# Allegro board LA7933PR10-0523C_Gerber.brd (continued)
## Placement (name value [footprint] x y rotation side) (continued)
Q55  -  [SSM3K7002FU_SC70-3]  288.59 61.86 270 bottom
Q56  -  [DMN3030LSS-13_SOP8L-8]  290.04 49.64 0 bottom
Q58  -  [SI3456DDV-T1-GE3_TSOP6]  138.23 147.7 90 top
Q59  -  [SSM3K7002FU_SC70-3]  294.17 54.45 270 bottom
Q60  -  [SSM3K7002FU_SC70-3]  151.16 154.1 90 top
Q61  -  [SSM3K7002FU_SC70-3]  207.87 54.04 0 bottom
Q63  -  [SI4164DY-T1-GE3_SO8]  47.47 132.3 0 top
Q65  -  [SSM3K7002FU_SC70-3]  129.57 32.83 90 top
Q66  -  [SSM3K7002FU_SC70-3]  9.31 133.92 90 bottom
Q67  -  [SSM3K7002FU_SC70-3]  216.18 90.74 90 bottom
Q68  -  [SSM3K7002FU_SC70-3]  190.53 150.43 270 bottom
Q69  -  [SSM3K7002FU_SC70-3]  290.17 55.88 0 bottom
Q70  -  [SSM3K7002FU_SC70-3]  43.53 131.82 0 bottom
Q71  -  [SSM3K7002FU_SC70-3]  125.07 72.27 0 top
Q72  -  [SSM3K7002FU_SC70-3]  235.93 53.98 180 bottom
Q73  -  [SSM3K7002FU_SC70-3]  101.77 135.45 270 top
Q74  -  [DMN66D0LDW-7_SOT363-6]  233.13 59.18 0 bottom
Q75  -  [PDTA114EU_SC70-3]  231.24 59.03 0 bottom
Q76  -  [SI4800BDY-T1-E3_SO8]  196.09 171.39 270 bottom
Q77  -  [SSM3K7002FU_SC70-3]  103.29 159.32 270 top
Q78  -  [DMN66D0LDW-7_SOT363-6]  225.76 64.51 0 bottom
Q79  -  [PDTA114EU_SC70-3]  226.16 59.03 0 bottom
Q80  -  [PDTA114EU_SC70-3]  241.65 62 180 bottom
Q84  -  [DMN66D0LDW-7_SOT363-6]  280.07 89.36 270 bottom
Q85  -  [SSM3K7002FU_SC70-3]  98.72 159.32 270 top
Q86  -  [PDTA114EU_SC70-3]  228.7 59.03 0 bottom
Q87  -  [SSM3K7002FU_SC70-3]  183.42 173.8 270 bottom
Q88  -  [SSM3K7002FU_SC70-3]  46.33 165.48 0 top
Q90  -  [PMV65XP_SOT23-3]  261.09 64.35 0 bottom
Q91  -  [PMV65XP_SOT23-3]  256.89 62.27 180 bottom
Q110  -  [DMN66D0LDW-7_SOT363-6]  108.49 136.32 90 top
Q113  -  [DMN66D0LDW-7_SOT363-6]  111.16 140.67 270 top
Q115  -  [PMST3904_SOT323-3]  147.93 165 180 top
Q124  -  [DMN66D0LDW-7_SOT363-6]  182.08 94.87 0 top
Q186  -  [SI4835DDY-T1-GE3_SO8]  186.05 171.64 270 bottom
Q294  -  [DMN66D0LDW-7_SOT363-6]  194.52 79.75 0 bottom
Q295  -  [DMN66D0LDW-7_SOT363-6]  203.49 151.21 270 bottom
Q297  -  [DMN66D0LDW-7_SOT363-6]  138.16 139.95 180 top
Q300  -  [DMN66D0LDW-7_SOT363-6]  183.6 59.57 0 top
Q301  -  [DMN66D0LDW-7_SOT363-6]  26.37 18.54 0 bottom
Q303  -  [DMN66D0LDW-7_SOT363-6]  129.78 26.67 180 top
Q304  -  [DMN66D0LDW-7_SOT363-6]  46.22 127.25 180 top
Q305  -  [DMN66D0LDW-7_SOT363-6]  14.72 132.72 180 bottom
Q306  -  [DMN66D0LDW-7_SOT363-6]  133.85 155.19 180 top
Q310  -  [DMN66D0LDW-7_SOT363-6]  176.7 108.63 90 bottom
Q311  -  [DMN66D0LDW-7_SOT363-6]  106.97 130.73 90 top
Q312  -  [DMN66D0LDW-7_SOT363-6]  157.77 155.37 90 top
Q313  -  [DMN66D0LDW-7_SOT363-6]  17.95 153.11 270 top
Q318  -  [DMN66D0LDW-7_SOT363-6]  291 105.59 90 bottom
Q321  -  [DMN66D0LDW-7_SOT363-6]  235.67 59.18 0 bottom
Q322  -  [DMN66D0LDW-7_SOT363-6]  36.31 150.87 180 top
Q326  -  [DMN66D0LDW-7_SOT363-6]  44.74 137.87 270 bottom
Q335  -  [DMN66D0LDW-7_SOT363-6]  46.22 151.96 180 bottom
Q336  -  [DMN66D0LDW-7_SOT363-6]  48.87 151.95 180 bottom
Q337  -  [DMN66D0LDW-7_SOT363-6]  54.8 156.53 270 bottom
Q338  -  [SSM3K7002FU_SC70-3]  279.79 85.84 0 bottom
Q339  -  [DMN66D0LDW-7_SOT363-6]  292.09 63 180 bottom
Q340  -  [DMN66D0LDW-7_SOT363-6]  293.2 64.89 0 bottom
QC1  -  [SSM3K7002FU_SC70-3]  96.18 82.61 270 top
QC2  -  [BSS138W-7-F_SOT323-3]  115.67 40.52 180 top
QC3  -  [AO4304L_SO8]  119.69 58.1 270 top
QC4  -  [NTR4503NT1G_SOT23-3]  117.22 77.79 90 top
QC5  -  [DMN66D0LDW-7_SOT363-6]  117.13 48.94 90 top
QD1  -  [BSS138-G_SOT23-3]  124.81 12.74 0 top
QD2  -  [BSS138-G_SOT23-3]  124.81 18.58 0 top
QH1  -  [BSS138W-7-F_SOT323-3]  24.48 96.52 0 top
QH2  -  [SSM3K7002FU_SC70-3]  28.04 96.52 180 top
QH4  -  [SSM3K7002FU_SC70-3]  10.96 123.25 90 top
QH5  -  [DMN66D0LDW-7_SOT363-6]  6.01 107.9 270 top
QH6  -  [SSM3K7002FU_SC70-3]  8.8 125.67 270 top
QH7  -  [SSM3K7002FU_SC70-3]  12.36 129.35 270 top
R1  -  [R_0402]  199.9 148.53 0 bottom
R2  -  [R_0402]  199.78 147.51 0 bottom
R3  -  [R_0402]  194.92 129.06 270 bottom
R4  -  [R_0402]  209.87 152.68 180 top
R5  -  [R_0402]  193.9 129.06 270 bottom
R6  -  [R_0402]  209.31 103.49 180 bottom
R7  -  [R_0402]  210.38 130.37 180 top
R8  -  [R_0402]  209.87 158.2 180 top
R9  -  [R_0402]  209.31 102.53 180 bottom
R10  -  [R_0402]  209.87 157.25 180 top
R11  -  [R_0402]  211.24 153.68 180 top
R12  -  [R_0402]  272.13 69.19 90 bottom
R13  -  [R_0402]  240.13 81.31 270 bottom
R14  -  [R_0402]  173.94 173.33 90 top
R15  -  [R_0402]  270.36 79.66 270 bottom
R16  -  [R_0402]  267.31 79.66 270 bottom
R17  -  [R_0402]  238.86 62.84 90 bottom
R18  -  [R_0402]  266.29 79.66 270 bottom
R21  -  [R_0402]  271.37 79.66 270 bottom
R22  -  [R_0402]  270.1 69.19 90 bottom
R23  -  [R_0402]  269.09 69.19 90 bottom
R24  -  [R_0402]  266.04 69.19 90 bottom
R25  -  [R_0402]  265.02 69.19 90 bottom
R26  -  [R_0402]  260.2 69.19 90 bottom
R27  -  [R_0402]  258.16 79.66 270 bottom
R28  -  [R_0402]  255.12 79.66 270 bottom
R29  -  [R_0402]  254.1 79.66 270 bottom
R30  -  [R_0402]  259.18 79.66 270 bottom
R31  -  [R_0402]  258.16 69.19 90 bottom
R32  -  [R_0402]  257.15 69.19 90 bottom
R33  -  [R_0402]  254.1 69.19 90 bottom
R34  -  [R_0402]  253.08 69.19 90 bottom
R35  -  [R_0402]  16.07 91.38 180 bottom
R36  -  [R_0402]  209.3 136.08 0 top
R37  -  [R_0402]  200.54 152.34 0 bottom
R38  -  [R_0402]  210.38 131.38 180 top
R39  -  [R_0402]  205.46 83.09 270 bottom
R40  -  [R_0402]  206.38 85.15 0 bottom
R41  -  [R_0402]  206.38 84.14 0 bottom
R42  -  [R_0402]  214.97 80.48 90 bottom
R43  -  [R_0402]  66.39 164.69 90 top
R44  -  [R_0402]  68.93 164.69 90 top
R45  -  [R_1206]  31.68 158.8 180 top
R46  -  [R_0402]  216.73 84.14 180 bottom
R47  -  [R_0402]  66.24 167.64 90 bottom
R48  -  [R_0402]  67.61 167.64 90 bottom
R49  -  [R_1206]  76.05 168.97 180 top
R50  -  [R_0402]  70.2 166.98 90 top
R51  -  [R_0402]  206.38 86.17 0 bottom
R52  -  [R_0402]  65.12 166.98 90 top
R53  -  [R_0402]  49.38 159.03 270 bottom
R54  -  [R_0402]  53.19 159.03 270 bottom
R55  -  [R_0402]  56.23 159.03 270 bottom
R56  -  [R_0402]  287.79 81.22 0 bottom
R57  -  [R_0402]  46.24 147.16 90 bottom
R58  -  [R_0402]  49.09 141.8 180 bottom
R59  -  [R_0402]  290.77 81.22 180 bottom
R60  -  [R_0402]  197.45 86.47 90 top
R61  -  [R_0402]  39.46 140.17 90 top
R62  -  [R_0402]  276.99 75.63 0 bottom
R63  -  [R_0402]  49.09 142.81 180 bottom
R64  -  [R_0402]  38.5 140.17 90 top
R65  -  [R_0402]  45.2 150.06 270 bottom
R66  -  [R_0402]  47.61 140 90 top
R67  -  [R_0402]  45.2 147.18 90 bottom
R68  -  [R_0402]  48.61 139.99 90 top
R69  -  [R_0402]  45.23 146.05 0 bottom
R70  -  [R_0402]  49.85 146.11 180 bottom
R71  -  [R_0402]  46.23 150.04 270 bottom
R72  -  [R_0402]  38.48 151.94 180 top
R73  -  [R_0402]  38.47 153 180 top
R74  -  [R_0402]  40.49 150.4 270 bottom
R75  -  [R_0402]  276.99 73.6 0 bottom
R76  -  [R_0402]  276.99 71.57 0 bottom
R77  -  [R_0402]  277.94 72.58 180 bottom
R78  -  [R_0402]  286.36 67.53 90 bottom
R79  -  [R_0402]  287.37 68.48 270 bottom
R80  -  [R_0402]  276.99 70.55 0 bottom
R81  -  [R_0402]  277.94 69.53 180 bottom
R82  -  [R_0402]  206.42 82.14 270 bottom
R83  -  [R_0402]  214.04 81.43 270 bottom
R84  -  [R_0402]  207.53 87.18 90 bottom
R85  -  [R_0402]  217.99 84.35 0 bottom
R86  -  [R_0402]  207.72 83.13 180 bottom
R87  -  [R_0402]  215.78 83.24 0 bottom
R88  -  [R_0402]  215.03 82.32 0 bottom
R89  -  [R_0402]  205.4 85.15 90 bottom
R90  -  [R_0402]  207.34 82.14 270 bottom
R91  -  [R_0402]  215.96 86.25 90 bottom
R92  -  [R_0402]  208.29 82.14 270 bottom
R93  -  [R_0402]  215.04 86.25 90 bottom
R94  -  [R_0402]  259.91 66.49 180 bottom
R95  -  [R_0402]  256.93 66.49 0 bottom
R102  -  [R_0402]  232.64 80.47 270 bottom
R103  -  [R_0402]  268.32 79.66 270 bottom
R104  -  [R_0402]  268.07 69.19 90 bottom
R105  -  [R_0402]  265.28 79.66 270 bottom
R106  -  [R_0402]  267.05 69.19 90 bottom
R107  -  [R_0402]  269.34 79.66 270 bottom
R108  -  [R_0402]  271.12 69.19 90 bottom
R109  -  [R_0402]  257.15 79.66 270 bottom
R110  -  [R_0402]  253.08 79.66 270 bottom
R111  -  [R_0402]  259.18 69.19 90 bottom
R112  -  [R_0402]  256.13 79.66 270 bottom
R113  -  [R_0402]  256.13 69.19 90 bottom
R114  -  [R_0402]  255.12 69.19 90 bottom
R158  -  [R_0402]  73 161.9 90 bottom
R159  -  [R_0402]  74.73 140.11 270 top
R160  -  [R_0402]  73.98 142.32 180 bottom
R161  -  [R_0402]  69.98 161.99 0 bottom
R162  -  [R_0402]  68.93 162.91 270 bottom
R184  -  [R_1206]  290.68 136.46 180 top
R207  -  [R0603_0OHM]  81.15 138.75 90 top
R208  -  [R0603_0OHM]  65.25 153.8 270 top
R213  -  [R_0603]  220.97 87.05 90 bottom
R222  -  [R_0402]  67.55 152.5 90 top
R268  -  [R_0603]  148.64 170.75 180 top
R269  -  [R_0402]  197.97 78.84 90 bottom
R274  -  [R_0603]  191.57 168.72 180 top
R275  -  [R_0402]  193.9 169.45 270 top
R278  -  [R_0402]  192.89 168.5 90 top
R289  -  [R_0402]  142.09 154.21 270 top
R294  -  [R_0402]  192.41 77.79 0 bottom
R301  -  [R_0402]  193.36 80.33 180 bottom
R305  -  [R_0402]  196.95 79.79 270 bottom
R336  -  [R_0402]  50.77 152.71 90 top
R339  -  [R_0402]  47.92 152.72 90 top
R340  -  [R_0402]  46.27 164.28 0 top
R341  -  [R_0402]  45.22 164.86 180 top
R385  -  [R_0402]  144.12 154.21 270 top
R388  -  [R_0402]  133.93 157.54 180 top
R389  -  [R_0402]  148.15 158.81 180 top
R390  -  [R_0402]  144.12 165.45 90 top
R391  -  [R_0402]  150.94 158.81 180 top
R392  -  [R_0402]  140.31 165.2 90 top
R393  -  [R_0402]  139.01 153.99 180 top
R395  -  [R_0402]  150.94 160.85 180 top
R396  -  [R_0402]  150.94 161.86 180 top
R397  -  [R_0402]  146.15 166.4 270 top
R398  -  [R_0402]  148.15 163.89 180 top
R399  -  [R_0402]  149.71 168.94 270 top
R400  -  [R_0402]  147.17 168.94 270 top
R401  -  [R_0402]  148.44 168.94 270 top
R402  -  [R_0402]  149.99 159.83 0 top
R403  -  [R_0402]  148.15 155.77 180 top
R404  -  [R_0402]  147.2 156.78 0 top
R405  -  [R_0402]  148.15 157.8 180 top
R406  -  [R_0402]  133.93 158.56 180 top
R407  -  [R_0402]  148.15 159.83 180 top
R408  -  [R_0402]  150.94 157.8 180 top
R409  -  [R_0402]  219.71 87.95 270 bottom
R412  -  [R_0402]  67.19 152.04 0 bottom
R413  -  [R_0402]  72.49 150.21 90 bottom
R414  -  [R_0402]  67.19 151.03 0 bottom
R415  -  [R_0402]  290.42 67.53 90 bottom
R418  -  [R_0402]  158.3 148.58 180 top
R419  -  [R_0402]  10.74 130.87 180 top
R420  -  [R_0402]  158.31 149.59 180 top
R421  -  [R_0402]  66.87 156.27 180 bottom
R422  -  [R_0402]  75.28 140.24 270 bottom
R423  -  [R_0402]  74.27 139.29 90 bottom
R427  -  [R_0402]  16.83 137.22 180 top
R428  -  [R_0402]  16.83 138.24 180 top
R429  -  [R_0402]  6.29 118.05 180 top
R430  -  [R_0402]  6.29 117.03 180 top
R431  -  [R_0402]  82.38 133.14 270 top
R451  -  [R_0402]  32.87 162.78 90 top
R452  -  [R_0402]  33.88 162.78 90 top
R453  -  [R_0402]  30.83 162.78 90 top
R454  -  [R_0402]  31.85 162.78 90 top
R455  -  [R_0402]  28.8 162.78 90 top
R456  -  [R_0402]  29.82 162.78 90 top
R457  -  [R_0402]  238.86 59.03 90 bottom
R458  -  [R_0402]  27.79 162.78 90 top
R459  -  [R_0402]  26.77 162.78 90 top
R460  -  [R_0402]  38.2 165.2 90 top
R461  -  [R_0402]  37.18 165.2 90 top
R491  -  [R_0402]  36.24 142.77 0 top
R492  -  [R_0402]  111.35 142.59 90 top
R499  -  [R_0402]  185.77 56.23 90 top
R500  -  [R_0402]  182.47 60.3 90 top
R501  -  [R_0402]  129.61 102.05 180 top
R502  -  [R_0402]  124.97 98.62 0 top
R503  -  [R_0402]  125.83 107.22 270 top
R504  -  [R_0402]  191.11 56.83 270 top
R505  -  [R_0402]  184.76 57.18 270 top
R506  -  [R_0402]  190.09 56.83 270 top
R513  -  [R_0402]  184.79 54.67 0 top
R514  -  [R_0402]  26.39 18.19 270 top
R515  -  [R_0402]  27.33 15.62 90 top
R516  -  [R_0402]  27.02 14.32 90 bottom
R517  -  [R_0402]  27.06 27.75 0 bottom
R518  -  [R_0402]  41.76 137.26 90 bottom
R519  -  [R_0402]  208.5 111.34 0 bottom
R545  -  [R_0402]  130.37 161.86 180 top
R546  -  [R_0402]  130.37 163.13 180 top
R547  -  [R_0402]  120.75 167.16 270 top
R548  -  [R_0805]  115.37 163.64 180 top
R549  -  [R_0402]  117.74 164.15 0 top
R551  -  [R0402_0OHM]  130.37 157.29 180 top
R552  -  [R0402_0OHM]  130.37 160.85 180 top
R553  -  [R_0402]  117.74 167.2 0 top
R554  -  [R_0402]  117.74 166.18 0 top
R555  -  [R0402_0OHM]  117.74 163.13 0 top
R557  -  [R_0402]  118.69 165.16 180 top
R561  -  [R_0402]  129.42 159.83 0 top
R562  -  [R_0402]  118.69 155 180 top
R563  -  [R_1206]  134.21 147.64 180 top
R564  -  [R_0402]  137.99 141.03 180 top
R565  -  [R_0402]  137.04 136.97 0 top
R571  -  [R_0402]  82.8 157.51 270 top
R572  -  [R_0402]  90.68 157.51 270 top
R573  -  [R_0402]  84.33 157.51 270 top
R574  -  [R_0402]  91.95 157.51 270 top
R575  -  [R_0402]  94.08 158.85 90 bottom
R576  -  [R_0402]  93.06 158.85 90 bottom
R577  -  [R_0402]  89.21 159.02 0 bottom
R578  -  [R_0402]  89.21 159.97 0 bottom
R585  -  [R_0402]  170.25 152.85 270 bottom
R589  -  [R_0402]  170.03 155.22 270 top
R656  -  [R_0402]  170.03 95.53 270 top
R657  -  [R_0402]  165.96 94.59 90 top
R658  -  [R_0402]  172.06 94.59 90 top
R659  -  [R_0402]  164.95 95.53 270 top
R660  -  [R_0402]  171.04 95.53 270 top
R690  -  [R_0402]  188.06 101.28 270 bottom
R691  -  [R_0402]  175.87 86.68 90 bottom
R692  -  [R_0402]  188.07 103.18 270 bottom
R693  -  [R_0402]  177.46 85.29 180 bottom
R694  -  [R_0402]  299.88 110.2 270 bottom
R700  -  [R_0402]  193.14 102.65 270 bottom
R702  -  [R0402_0OHM]  200.51 86.97 90 bottom
R703  -  [R0402_0OHM]  190.6 102.65 270 bottom
R704  -  [R0402_0OHM]  107.58 151.96 0 top
R705  -  [R_0402]  182.73 98.65 90 top
R706  -  [R_0402]  183.74 98.65 90 top
R707  -  [R0402_0OHM]  201.52 86.97 90 bottom
R708  -  [R_0402]  181.2 101.7 90 bottom
R709  -  [R0402_0OHM]  179.13 87.27 90 bottom
R713  -  [R0402_0OHM]  21.94 152.24 90 top
R715  -  [R_0402]  178.66 106.27 90 bottom
R716  -  [R_0402]  177.65 101.7 90 bottom
R717  -  [R_0402]  173.93 109.03 180 bottom
R718  -  [R_0402]  181.71 98.65 90 top
R719  -  [R_0402]  107.58 160.08 0 top
R720  -  [R_0402]  176.63 107.22 270 bottom
R721  -  [R_0402]  102.75 130.62 0 top
R722  -  [R_0402]  103.7 131.64 180 top
R723  -  [R_0402]  98.43 134.94 0 top
R724  -  [R0402_0OHM]  178.86 168.11 180 bottom
R727  -  [R_0402]  108.41 132.2 270 top
R730  -  [R0402_0OHM]  179.42 161.9 90 top
R731  -  [R_0402]  160.12 157.76 270 top
R732  -  [R_0402]  160.63 161.07 270 top
R733  -  [R_0402]  159.1 155.48 270 top
R734  -  [R_0402]  15.88 153.48 0 top
R735  -  [R_0402]  154.8 156.57 270 top
R736  -  [R_0402]  10.26 159.36 90 top
R737  -  [R_0402]  18.86 150.56 180 top
R738  -  [R_0402]  20.93 153.19 270 top
R739  -  [R_0402]  18.42 154.24 0 top
R740  -  [R_0402]  36.17 146.66 90 top
R741  -  [R0402_0OHM]  232.26 61.5 270 bottom
R742  -  [R_0402]  9.24 159.36 90 top
R743  -  [R_0402]  289.66 109.06 90 bottom
R744  -  [R_0402]  290.68 109.06 90 bottom
R745  -  [R_0402]  288.64 109.06 90 bottom
R746  -  [R_0402]  287.63 109.06 90 bottom
R747  -  [R_0402]  294.58 61.91 180 bottom
R748  -  [R_0402]  297.61 116.45 90 bottom
R749  -  [R_0402]  296.59 116.45 90 bottom
R750  -  [R_0402]  283.71 97.85 0 top
R751  -  [R_0402]  283.71 96.84 0 top
R752  -  [R_0402]  283.7 100.19 0 top
R753  -  [R_0402]  283.7 99.17 0 top
R754  -  [R_0402]  282.78 93.49 0 top
R755  -  [R_0402]  115.92 126.34 90 top
R756  -  [R_0402]  113.89 113.06 270 bottom
R757  -  [R_0402]  91.29 113.06 270 bottom
R758  -  [R_0402]  212.61 108.58 270 bottom
R759  -  [R_0402]  157.36 139.26 0 bottom
R760  -  [R_0402]  227.21 75.86 0 bottom
R761  -  [R_0402]  245.69 77.53 180 bottom
R762  -  [R_0402]  47.85 126.27 270 top
R763  -  [R_0402]  245.69 76.52 180 bottom
R764  -  [R_0402]  282.78 94.5 0 top
R765  -  [R_0402]  239.88 62.84 90 bottom
R766  -  [R_0402]  232.26 62.84 90 bottom
R767  -  [R_0402]  233.59 81.3 270 bottom
R768  -  [R_0402]  234.9 82.97 45 bottom
R769  -  [R_0402]  234.54 81.31 270 bottom
R770  -  [R_0402]  228.16 66.49 180 bottom
R771  -  [R0402_0OHM]  244.74 66.87 0 bottom
R772  -  [R_0402]  247.53 75.73 0 bottom
R773  -  [R_0402]  272.39 79.66 270 bottom
R774  -  [R_0402]  245.69 74.49 180 bottom
R775  -  [R_0402]  241.15 81.31 270 bottom
R776  -  [R_0402]  239.88 59.03 90 bottom
R777  -  [R_0402]  228.16 68.38 180 bottom
R778  -  [R_0402]  243.18 81.31 270 bottom
R779  -  [R_0402]  233.27 62.84 90 bottom
R780  -  [R_0402]  228.16 69.32 180 bottom
R781  -  [R0402_0OHM]  47.85 123.03 90 top
R782  -  [R_0402]  228.17 70.24 180 bottom
R783  -  [R_0402]  21.18 159.54 270 top
R784  -  [R_0402]  285.33 62.18 270 bottom
R785  -  [R_0402]  35.66 153.19 270 top
R786  -  [R_0402]  234.29 63.78 270 bottom
R787  -  [R_0402]  245.69 75.5 180 bottom
R788  -  [R_0402]  236.57 81.31 270 bottom
R789  -  [R_0402]  231.24 63.78 270 bottom
R790  -  [R_0402]  244.74 70.42 0 bottom
R791  -  [R_0402]  228.17 73.06 180 bottom
R792  -  [R_0402]  27.5 23.94 180 top
R793  -  [R_0402]  236.83 63.78 270 bottom
R794  -  [R_0402]  227.21 74.93 0 bottom
R795  -  [R_0402]  228.17 72.11 180 bottom
R796  -  [R_0402]  26.55 24.96 0 top
R797  -  [R0402_0OHM]  242.16 81.31 270 bottom
R798  -  [R_0402]  227.21 76.78 0 bottom
R799  -  [R_0402]  158.31 140.27 180 bottom
R800  -  [R_0402]  245.69 73.47 180 bottom
R801  -  [R_0603]  288.95 143.83 0 top
R802  -  [R_0402]  227.21 65.56 0 bottom
R803  -  [R_0402]  244.74 72.45 0 bottom
R804  -  [R_0402]  228.16 67.42 180 bottom
R805  -  [R_0402]  245.69 79.57 180 bottom
R806  -  [R_0402]  126.37 24.7 0 top
R807  -  [R_0402]  248.48 77.53 180 bottom
R808  -  [R0402_0OHM]  126.37 25.72 0 top
R809  -  [R_0402]  264.01 69.19 90 bottom
R810  -  [R_0402]  157.36 152.64 0 bottom
R811  -  [R_0402]  158.31 153.66 180 bottom
R812  -  [R_0402]  176.58 150.94 180 top
R813  -  [R_0402]  260.2 79.66 270 bottom
R814  -  [R_0402]  176.6 147.89 180 bottom
R815  -  [R0402_0OHM]  162.66 155.22 270 bottom
R816  -  [R_0402]  289.88 60.9 180 bottom
R817  -  [R_0402]  157.36 138.24 0 bottom
R818  -  [R_0402]  166.98 155.22 270 bottom
R819  -  [R_0402]  157.36 153.61 0 top
R820  -  [R_0402]  166.98 155.22 270 top
R821  -  [R_0402]  158.31 142.3 180 bottom
R822  -  [R_0402]  175.65 150.94 0 bottom
R823  -  [R_0402]  168.98 142.05 180 bottom
R824  -  [R_0402]  171.04 158.27 270 top
R825  -  [R_0402]  158.31 152.59 180 top
R826  -  [R_0402]  252.07 69.19 90 bottom
R827  -  [R_0402]  176.6 151.96 180 top
R828  -  [R_0402]  176.6 151.96 180 bottom
R829  -  [R_0402]  175.65 149.92 0 bottom
R830  -  [R_0402]  274.13 75.76 180 bottom
R831  -  [R_0402]  274.13 74.74 180 bottom
R832  -  [R_0402]  261.43 76.01 180 bottom
R833  -  [R_0402]  261.43 74.99 180 bottom
R835  -  [R_0402]  167.99 154.28 90 top
R836  -  [R_0402]  170.03 157.32 90 top
R838  -  [R_0402]  158.3 150.56 180 top
R841  -  [R_0402]  158.31 149.59 180 bottom
R843  -  [R_0402]  179.65 148.4 180 top
R845  -  [R_0402]  175.65 143.32 0 top
R846  -  [R_0402]  171.33 146.37 0 bottom
R847  -  [R_0402]  207.78 116.78 0 top
R848  -  [R_0402]  207.78 119.83 0 top
R849  -  [R_0402]  211.73 118.58 0 top
R850  -  [R_0402]  213.61 107.56 90 top
R851  -  [R_0402]  175.65 144.34 0 top
R852  -  [R_0402]  171.33 145.1 0 bottom
R853  -  [R0402_0OHM]  208.73 115.76 180 top
R854  -  [R_0402]  158.31 147.38 180 bottom
R855  -  [R0402_0OHM]  211.73 117.56 0 top
R856  -  [R_0402]  158.35 147.55 180 top
R858  -  [R_0402]  207.78 118.81 0 top
R859  -  [R_0402]  214.39 105.54 180 top
R860  -  [R_0402]  207.78 117.79 0 top
R861  -  [R_0402]  214.29 106.59 180 top
R862  -  [R0402_0OHM]  175.65 155 0 top
R863  -  [R_0402]  175.65 152.97 0 top
R864  -  [R_0402]  214.39 104.59 180 top
R867  -  [R0402_0OHM]  165.96 155.22 270 bottom
R869  -  [R_0402]  176.6 145.35 180 top
R870  -  [R_0402]  164.95 155.22 270 bottom
R871  -  [R_0402]  157.4 145.34 0 top
R872  -  [R_0402]  160.63 155.22 270 bottom
R873  -  [R_0402]  169.01 94.59 90 top
R875  -  [R_0402]  157.36 143.32 0 bottom
R876  -  [R_0402]  157.36 141.29 0 bottom
R879  -  [R_0402]  161.64 155.22 270 bottom
R880  -  [R_0402]  165.71 137.77 90 top
R881  -  [R_0402]  163.2 142.05 0 bottom
R882  -  [R_0402]  166.72 137.77 90 top
R883  -  [R_0402]  26.52 9.5 90 top
R884  -  [R_0402]  158.3 150.61 180 bottom
R885  -  [R_0402]  168.76 138.71 270 top
R886  -  [R_0402]  158.31 146.37 180 bottom
R887  -  [R_0402]  161.9 138.71 270 top
R888  -  [R_0402]  244.74 71.44 0 bottom
R889  -  [R_0402]  176.58 142.3 180 top
R890  -  [R_0402]  45.48 107.16 0 top
R891  -  [R_0402]  45.48 106.15 0 top
R892  -  [R_0402]  176.6 148.91 180 bottom
R893  -  [R_0402]  178 153.06 0 top
R894  -  [R_0402]  56.46 107.25 180 bottom
R895  -  [R_0402]  59.76 100.9 180 top
R897  -  [R_0402]  44.39 101.16 180 top
R898  -  [R_0402]  56.46 108.52 180 bottom
R899  -  [R_0402]  46.43 108.2 180 top
R900  -  [R_0402]  46.3 103.19 180 top
R901  -  [R_0402]  46.42 111.24 180 top
R904  -  [R_0402]  296.52 109.06 90 bottom
R905  -  [R_0402]  14.29 131.64 180 bottom
R906  -  [R_0402]  206.09 53.12 90 bottom
R907  -  [R_0402]  13.34 135.7 0 bottom
R908  -  [R_0402]  8.7 126.81 180 bottom
R909  -  [R_0402]  45.91 124.02 180 top
R910  -  [R_0402]  45.48 109.22 0 top
R911  -  [R_0402]  129.35 29.02 180 top
R912  -  [R_0402]  196.44 54.32 270 bottom
R913  -  [R_0402]  44.39 100.14 180 top
R914  -  [R_0402]  172.06 157.32 90 top
R915  -  [R_0402]  128.4 23.69 0 top
R916  -  [R_0603]  150.01 156.53 0 top
R917  -  [R_0402]  139.01 151.96 180 top
R918  -  [R_0402]  132.21 151.96 0 top
R919  -  [R_0402]  133.16 150.94 180 top
R920  -  [R_0402]  292.55 52.45 0 bottom
R921  -  [R_0402]  286.61 50.07 270 bottom
R922  -  [R_0402]  128.4 31.05 0 top
R923  -  [R_0402]  215.81 88.87 90 bottom
R924  -  [R_0402]  191.87 151.41 270 bottom
R925  -  [R_0402]  45.79 132.14 180 bottom
R926  -  [R_0402]  124.09 70.93 0 top
R927  -  [R_0603]  233.64 55.39 270 bottom
R928  -  [R_0402]  7.14 133.55 0 bottom
R929  -  [R_0603]  287.88 53.96 90 bottom
R930  -  [R_0402]  46.84 128.62 90 top
R931  -  [R_0402]  45.82 134.72 90 top
R932  -  [R_0402]  233.27 61.5 270 bottom
R934  -  [R_0402]  231.24 60.55 90 bottom
R935  -  [R_0402]  176.03 174.52 180 top
R936  -  [R_0402]  59.76 99.38 180 top
R937  -  [R_0402]  229.97 60.55 90 bottom
R938  -  [R_0402]  291.18 103.48 90 bottom
R939  -  [R_0402]  226.16 60.55 90 bottom
R940  -  [R_0402]  184.76 174.27 270 bottom
R941  -  [R_0402]  292.2 104.42 270 bottom
R942  -  [R_0402]  241.4 59.97 270 bottom
R943  -  [R_0402]  228.7 60.55 90 bottom
R944  -  [R_0402]  227.18 60.55 90 bottom
R955  -  [R_0402]  279.15 90.49 0 bottom
R956  -  [R_0402]  278.2 90.49 180 bottom
R963  -  [R_0402]  55.51 105.98 0 bottom
R1068  -  [R0402_0OHM]  163.68 155.22 270 top
R1118  -  [R_0402]  157.36 145.35 0 bottom
R1121  -  [R_0402]  65.03 134.43 0 top
R1122  -  [R_0402]  71.73 140.24 270 top
R1123  -  [R_0402]  64.01 132.97 0 top
R1124  -  [R_0402]  70.71 140.24 270 top
R1125  -  [R_0402]  162.91 138.71 270 top
R1128  -  [R_0402]  41.25 165.2 90 top
R1133  -  [R_0402]  301.82 109.2 180 bottom
R1134  -  [R_0402]  301.82 110.21 180 bottom
R1137  -  [R_0402]  83.4 133.14 270 top
R1138  -  [R_0402]  82.45 134.07 0 top
R1144  -  [R0402_0OHM]  118.69 158.18 180 top
R1156  -  [R_0402]  162.66 154.28 90 top
R1157  -  [R0402_0OHM]  107.58 155 0 top
R1158  -  [R0402_0OHM]  108.53 157.04 180 top
R1159  -  [R_0402]  108.53 153.99 180 top
R1160  -  [R_0402]  107.58 156.02 0 top
R1161  -  [R_0402]  100.4 157.54 180 top
R1164  -  [R_0402]  40.23 165.2 90 top
R1165  -  [R_0402]  33.88 164.62 270 bottom
R1167  -  [R_0402]  96.85 160.51 90 top
R1169  -  [R_0402]  39.22 165.2 90 top
R1170  -  [R_0402]  97.94 162.01 0 top
R1171  -  [R_0402]  77.25 164.47 0 top
R1177  -  [R_0402]  157.36 151.63 0 bottom
R1178  -  [R_0402]  175.65 141.29 0 top
R1179  -  [R_0402]  176.6 149.92 180 top
R1180  -  [R0402_0OHM]  175.65 148.91 0 top
R1187  -  [R0402_0OHM]  119.81 167.16 270 top
R1191  -  [R_0402]  261.43 77.03 180 bottom
R1197  -  [R_0402]  160.88 137.77 90 top
R1207  -  [R_0402]  274.13 76.77 180 bottom
R1523  -  [R_0402]  115.38 139.51 180 top
R1530  -  [R_0402]  112.08 137.99 180 top
R1532  -  [R_0402]  105.51 137.32 270 top
R1537  -  [R_0402]  107.58 139 0 top
R1538  -  [R_0402]  113.89 142.63 90 top
R1539  -  [R_0402]  115.43 143.52 270 top
R1582  -  [R_0402]  235.56 81.31 270 bottom
R1611  -  [R_0402]  44.97 129.58 270 top
R1613  -  [R_0402]  277.19 83.85 270 bottom
R1614  -  [R_0402]  276.17 82.9 90 bottom
R1617  -  [R_0402]  138.06 152.97 0 top
R1618  -  [R_0402]  128.4 28 0 top
R1619  -  [R_0402]  13.34 130.62 0 bottom
R1620  -  [R_0402]  177.65 106.27 90 bottom
R1621  -  [R_0402]  182.73 56.23 90 top
R1622  -  [R_0402]  181.68 145.61 180 bottom
R1623  -  [R_0402]  178.66 148.94 90 bottom
R1624  -  [R_0402]  183.74 56.23 90 top
R1625  -  [R_0402]  102.75 132.65 0 top
R1626  -  [R_0402]  274.29 79.53 270 bottom
R1627  -  [R_0402]  27.28 18.45 270 top
R1628  -  [R_0402]  161.14 156.82 90 top
R1629  -  [R_0402]  16.86 151.23 90 top
R1630  -  [R_0402]  185.68 58.23 0 top
R1631  -  [R_0402]  294.59 53.56 270 bottom
R1632  -  [R_0402]  73.51 150.21 90 bottom
R1633  -  [R0402_0OHM]  179.68 148.94 90 bottom
R1638  -  [R_0402]  137.04 142.05 0 top
R1970  -  [R0402_0OHM]  193.94 156.53 0 top
R1971  -  [R_0402]  193.94 155.51 0 top
R1972  -  [R_0402]  209.78 159.18 180 top
R1976  -  [R0402_0OHM]  207.73 154.58 270 top
R2151  -  [R_0402]  46.62 156.01 270 bottom
R2152  -  [R_0402]  48.9 154.84 180 bottom
R2153  -  [R_0402]  45.69 156.01 270 bottom
R2154  -  [R_0402]  50.07 155.82 0 bottom
R2155  -  [R_0402]  44.72 156.16 270 bottom
R2156  -  [R_0402]  45.28 150.94 0 bottom
R2157  -  [R_0402]  43.78 156.16 270 bottom
R2158  -  [R_0402]  249.46 63.78 270 bottom
R2159  -  [R_0402]  181.99 142.11 180 bottom
R2160  -  [R_0402]  90.61 132.18 90 bottom
R2161  -  [R_0402]  52.9 153.2 0 bottom
R2162  -  [R_0402]  50.96 156.74 0 bottom
R2163  -  [R_0402]  53.85 154.15 180 bottom
R2164  -  [R_0402]  82.65 113.32 90 bottom
R2165  -  [R_0402]  83.67 113.32 90 bottom
R2166  -  [R_0402]  84.68 113.32 90 bottom
R2167  -  [R_0402]  85.7 113.32 90 bottom
R2168  -  [R_0402]  86.71 113.32 90 bottom
R2169  -  [R_0402]  87.73 113.32 90 bottom
R2170  -  [R_0402]  88.75 113.32 90 bottom
R2171  -  [R_0402]  89.76 113.32 90 bottom
R2172  -  [R_0402]  82.4 131.1 90 bottom
R2173  -  [R_0402]  83.31 131.1 90 bottom
R2174  -  [R_0402]  84.56 131.14 90 bottom
R2175  -  [R_0402]  85.52 131.14 90 bottom
R2176  -  [R_0402]  86.46 131.14 90 bottom
R2177  -  [R_0402]  87.48 131.14 90 bottom
R2178  -  [R_0402]  88.49 131.14 90 bottom
R2179  -  [R_0402]  89.51 131.14 90 bottom
R2180  -  [R_0402]  169.07 173.75 180 bottom
R2181  -  [R_0402]  169.07 174.68 180 bottom
R2182  -  [R_0402]  205.28 150.24 0 bottom
R2183  -  [R_0402]  205.28 151.19 0 bottom
R2184  -  [R_0402]  153.66 173.11 180 top
R2185  -  [R_0402]  153.66 175.15 180 top
R2186  -  [R_0402]  152.71 172.1 0 top
R2187  -  [R_0402]  152.71 174.13 0 top
R2188  -  [R_0402]  163.18 104.64 90 bottom
R2189  -  [R_0402]  165.42 104.45 90 bottom
R2190  -  [R_0402]  293.63 66.1 0 bottom
R2191  -  [R_0402]  292.68 61.91 180 bottom
R2192  -  [R_0402]  291.22 66.1 0 bottom
R2193  -  [R_0402]  289.41 64.29 270 bottom
R2200  -  [R_0402]  264.42 76.14 0 bottom
R2201  -  [R_0402]  271.34 81.34 180 bottom
R2202  -  [R_0402]  251.34 76.77 0 bottom
R2203  -  [R_0402]  259.15 81.34 180 bottom
RC1  -  [R_0402]  82.9 36.1 270 top
RC2  -  [R_0402]  83.63 50.94 180 bottom
RC3  -  [R_0402]  75.68 89 90 bottom
RC4  -  [R_0402]  92.81 81.89 90 top
RC5  -  [R_0402]  93.83 82.83 270 top
RC6  -  [R_0402]  94.59 89.44 270 top
RC7  -  [R_0402]  94.84 82.83 270 top
RC8  -  [R_0402]  67.98 88.08 0 bottom
RC9  -  [R_0402]  72.49 89 90 bottom
RC10  -  [R_0402]  73.51 89 90 bottom
RC11  -  [R_0402]  74.66 89 90 bottom
RC14  -  [R_0402]  70.12 84.77 180 bottom
RC15  -  [R_0402]  64.58 76.65 180 bottom
RC16  -  [R_0402]  65.99 85.08 270 bottom
RC17  -  [R0402_0OHM]  73.76 36.1 270 top
RC18  -  [R0402_0OHM]  74.78 36.1 270 top
RC19  -  [R_0402]  83.92 36.1 270 top
RC20  -  [R_0402]  84.94 36.1 270 top
RC21  -  [R_0402]  75.68 86.72 90 bottom
RC22  -  [R_0402]  66.39 82.83 270 bottom
RC23  -  [R_0402]  115.2 43.75 0 top
RC24  -  [R0402_0OHM]  69.44 82.83 270 bottom
RC25  -  [R0402_0OHM]  119.48 41.5 90 top
RC26  -  [R_0402]  118.46 41.5 90 top
RC27  -  [R0402_0OHM]  68.43 82.83 270 bottom
RC28  -  [R0402_0OHM]  59.5 78.55 180 top
RC30  -  [R_0402]  77.18 87.89 270 bottom
RC33  -  [R_0402]  73.02 81.76 90 top
RC37  -  [R_0402]  75.54 81.89 90 bottom
RC38  -  [R_0402]  77.66 90.25 180 top
RC41  -  [R_0402]  72.38 81.89 90 bottom
RC42  -  [R_0402]  67.99 90.09 270 bottom
RC43  -  [R_0402]  78.21 87.89 270 bottom
RC44  -  [R_0402]  75.53 79.36 90 bottom
RC45  -  [R_0402]  79.07 90.55 90 top
RC46  -  [R_0402]  68.06 84.8 180 bottom
RC47  -  [R_0402]  96.11 36.1 270 top
RC48  -  [R_0402]  95.1 36.1 270 top
RC49  -  [R_0402]  64.87 86.14 270 top
RC50  -  [R_0402]  104.53 70.42 0 bottom
RC51  -  [R_0402]  66.39 82.83 270 top
RC52  -  [R_0402]  74.52 81.89 90 bottom
RC53  -  [R_0402]  73.56 81.89 90 bottom
RC54  -  [R_0402]  59.96 76.25 180 bottom
RC55  -  [R_0402]  59.06 74.87 0 bottom
RC56  -  [R_0402]  59.03 73 90 bottom
RC57  -  [R_0402]  71.47 81.89 90 bottom
RC58  -  [R_0402]  67.41 81.89 90 bottom
RC59  -  [R_0402]  62.08 70.58 90 bottom
RC60  -  [R_0402]  61.06 71.53 270 bottom
RC61  -  [R_0402]  58.93 71.82 0 bottom
RC62  -  [R_0402]  70.46 81.89 90 bottom
RC63  -  [R_0402]  61.86 84.39 0 top
RC64  -  [R_0402]  62.84 82.52 90 top
RC65  -  [R_0402]  62.68 77.66 180 bottom
RC66  -  [R_0402]  58.52 72.42 270 top
RC67  -  [R_0402]  57.54 73.47 0 top
RC68  -  [R0402_0OHM]  59.54 72.49 90 top
RC69  -  [R0402_0OHM]  59.54 71.4 270 top
RC70  -  [R_0402]  91.03 35.15 90 top
RC71  -  [R_0402]  58.49 70.42 180 top
RC72  -  [R_0402]  92.05 36.1 270 top
RC73  -  [R_0402]  119.45 50.36 180 top
RC74  -  [R_0402]  115.89 74.23 180 top
RC75  -  [R_0402]  114.94 72.2 0 top
RC76  -  [R_0402]  116.15 47.82 180 top
RC77  -  [R_0402]  117.7 54.89 270 top
RC78  -  [R_0402]  114.94 75.25 0 top
RC79  -  [R_0402]  118.5 51.37 0 top
RC80  -  [R_0402]  117.23 75.25 0 top
RC81  -  [R_0402]  114.94 73.22 0 top
RC82  -  [R_0402]  119.45 48.32 180 top
RC83  -  [R0402_0OHM]  119.45 49.34 180 top
RC84  -  [R_0402]  59.54 77.5 270 top
RC85  -  [R_0402]  58.52 76.48 270 top
RC86  -  [R_0402]  59.54 75.47 270 top
RC87  -  [R_0402]  97.13 35.15 90 top
RC88  -  [R_0402]  99.92 35.15 90 top
RC89  -  [R_0402]  81.89 36.1 270 top
RD1  -  [R0402_0OHM]  128.81 13.81 90 top
RD2  -  [R0402_0OHM]  129.83 13.81 90 top
RD3  -  [R_0402]  131.9 29 180 top
RD4  -  [R_0402]  131.9 30.02 180 top
RD5  -  [R_0402]  122.27 14.76 270 top
RD6  -  [R_0402]  122.34 20.35 270 top
RD7  -  [R0402_0OHM]  130.62 63.56 180 top
RD8  -  [R_0402]  127.83 88.46 180 top
RD9  -  [R_0402]  127.83 89.47 180 top
RD10  -  [R0402_0OHM]  130.62 81.09 180 top
RD11  -  [R0402_0OHM]  130.62 82.11 180 top
RD12  -  [R_0402]  129.67 88.46 0 top
RD13  -  [R_0402]  129.67 89.47 0 top
RD14  -  [R0402_0OHM]  128.62 23.4 270 bottom
RD15  -  [R0402_0OHM]  129.64 23.4 270 bottom
RD16  -  [R0402_0OHM]  130.62 63.56 180 bottom
RD17  -  [R_0402]  130.88 76.01 180 bottom
RD18  -  [R_0402]  128.46 78.8 180 bottom
RD19  -  [R_0402]  129.93 77.03 0 bottom
RD20  -  [R_0402]  127.51 77.79 0 bottom
RD21  -  [R0402_0OHM]  146.02 92.05 90 bottom
RD22  -  [R0402_0OHM]  145.01 92.05 90 bottom
RD23  -  [R0402_0OHM]  164.69 23.4 270 top
RD24  -  [R0402_0OHM]  163.42 23.4 270 top
RD25  -  [R0402_0OHM]  161.68 63.06 0 top
RD26  -  [R_0402]  164.47 80.07 0 top
RD27  -  [R_0402]  164.47 77.03 0 top
RD28  -  [R_0402]  162.63 80.07 180 top
RD29  -  [R_0402]  162.63 77.03 180 top
RD30  -  [R0402_0OHM]  150.6 92.05 90 bottom
RD31  -  [R0402_0OHM]  152.04 92.05 90 bottom
RD32  -  [R0402_0OHM]  164.69 23.4 270 bottom
RD33  -  [R0402_0OHM]  163.42 23.4 270 bottom
RD34  -  [R0402_0OHM]  161.68 62.8 0 bottom
RD35  -  [R_0402]  146.91 92.05 90 bottom
RD36  -  [R_0402]  149.71 92.05 90 bottom
RD37  -  [R_0402]  147.8 92.99 270 bottom
RD38  -  [R_0402]  148.82 92.99 270 bottom
RD39  -  [R0402_0OHM]  154.02 92.05 90 bottom
RD40  -  [R0402_0OHM]  153.06 92.05 90 bottom
RE5  -  [R_0402]  171.04 108.05 90 top
RE6  -  [R_0402]  174.09 95.53 270 top
RE11  -  [R_0402]  105 113.06 270 bottom
RE12  -  [R_0402]  101.95 113.06 270 bottom
RH1  -  [R_0402]  56.01 80.58 0 top
RH2  -  [R_0402]  56.01 79.57 0 top
RH3  -  [R_0402]  59.5 80.58 180 top
RH4  -  [R_0402]  59.5 79.57 180 top
RH5  -  [R_0402]  72.11 112.55 270 top
RH6  -  [R_0402]  70.59 112.55 270 top
RH7  -  [R_0402]  74.14 112.55 270 top
RH8  -  [R_0402]  68.55 112.55 270 top
RH9  -  [R_0402]  67.54 112.55 270 top
RH10  -  [R_0402]  74.14 99.16 90 top
RH11  -  [R_0402]  10.29 117.41 0 top
RH12  -  [R_0402]  73.13 99.16 90 top
RH13  -  [R_0402]  72.11 99.16 90 top
RH14  -  [R_0402]  69.57 112.55 270 top
RH15  -  [R_0402]  14.32 114.33 270 top
RH16  -  [R_0402]  73.13 112.55 270 top
RH17  -  [R_0402]  68.05 99.16 90 top
RH18  -  [R_0402]  67.03 99.16 90 top
RH19  -  [R_0402]  76.17 99.16 90 top
RH20  -  [R_0402]  70.08 99.16 90 top
RH21  -  [R_0402]  65.51 112.55 270 top
RH22  -  [R_0402]  15.85 114.33 270 bottom
RH23  -  [R_0402]  15.88 116.9 0 bottom
RH24  -  [R_0402]  65.51 99.16 90 top
RH25  -  [R_0402]  18.17 120.21 0 bottom
RH26  -  [R_0402]  71.09 99.16 90 top
RH27  -  [R_0402]  16.61 132.62 270 top
RH28  -  [R_0402]  26.68 96.79 270 bottom
RH29  -  [R_0402]  13.34 123.51 0 top
RH30  -  [R_0402]  29.31 100.17 90 bottom
RH31  -  [R_0402]  15.59 132.62 270 top
RH32  -  [R_0402]  8.64 124.84 180 bottom
RH34  -  [R_0402]  69.06 99.16 90 top
RH35  -  [R_0402]  24.23 101.12 270 bottom
RH38  -  [R_0402]  9.79 111.32 0 top
RH39  -  [R_0402]  10.74 110.3 180 top
RH40  -  [R_0402]  29.56 108.43 90 bottom
RH41  -  [R_0402]  13.34 121.6 0 bottom
RH42  -  [R_0402]  28.97 110.34 0 bottom
RH43  -  [R_0402]  17.12 101.12 270 top
RH44  -  [R_0402]  15.09 101.12 270 bottom
RH45  -  [R_0402]  13.05 96.8 270 bottom
RH46  -  [R_0402]  31.6 101.12 270 top
RH47  -  [R_0402]  18.13 101.12 270 top
RH48  -  [R_0402]  16.1 101.12 270 bottom
RH49  -  [R_0402]  12.04 96.8 270 bottom
RH50  -  [R_0402]  16.03 136.89 270 bottom
RH51  -  [R_0402]  75.16 112.55 270 top
RH52  -  [R_0402]  23.21 101.12 270 top
RH53  -  [R_0402]  75.16 99.16 90 top
RH54  -  [R_0402]  23.63 96.79 270 bottom
RH59  -  [R_0402]  17.12 101.12 270 bottom
RH66  -  [R_0402]  10.74 129.1 180 top
RH74  -  [R_0402]  39.76 113.32 0 bottom
RH75  -  [R_0402]  38.68 113.32 180 bottom
RH76  -  [R_0402]  20.81 116.1 0 bottom
RH77  -  [R_0402]  19.86 116.1 180 bottom
RH78  -  [R_0402]  33.31 97.03 270 bottom
RH79  -  [R_0402]  32.29 97.03 270 bottom
RH80  -  [R_0402]  26.15 96.8 270 top
RH81  -  [R_0402]  19.15 101.12 270 top
RH82  -  [R0402_0OHM]  29.82 131.67 90 top
RH83  -  [R0402_0OHM]  30.83 131.67 90 top
RH85  -  [R0402_0OHM]  29.31 135.48 90 top
RH86  -  [R0402_0OHM]  28.29 135.48 90 top
RH87  -  [R_0402]  27.28 100.17 90 bottom
RH88  -  [R0402_0OHM]  27.79 131.67 90 bottom
RH90  -  [R0402_0OHM]  26.77 131.67 90 bottom
RH91  -  [R_0402]  44.9 122.09 0 top
RH92  -  [R0402_0OHM]  28.8 131.67 90 bottom
RH93  -  [R0402_0OHM]  29.82 131.67 90 bottom
RH94  -  [R_0402]  14.29 108.27 180 bottom
RH95  -  [R0402_0OHM]  27.54 138.29 0 bottom
RH96  -  [R0402_0OHM]  27.54 139.24 0 bottom
RH97  -  [R_0402]  10.74 109.28 180 bottom
RH98  -  [R_0402]  13.34 102.17 0 bottom
RH99  -  [R_0402]  26.74 131.64 180 top
RH100  -  [R_0402]  28.04 131.67 90 top
RH101  -  [R_0402]  13.34 110.3 0 bottom
RH102  -  [R_0402]  20.67 135.88 90 bottom
RH103  -  [R_0402]  19.66 135.89 90 top
RH105  -  [R_0402]  19.66 135.88 90 bottom
RH106  -  [R_0402]  14.29 109.28 180 bottom
RH111  -  [R_0402]  46.74 119.29 180 top
RH112  -  [R_0402]  46.3 112.84 180 top
RH113  -  [R0402_0OHM]  13.34 115.38 0 top
RH114  -  [R_0402]  13.34 107.25 0 top
RH116  -  [R0402_0OHM]  15.09 95.86 90 bottom
RH117  -  [R0402_0OHM]  10.74 113.35 180 bottom
RH118  -  [R_0402]  14.07 95.86 90 bottom
RH120  -  [R0402_0OHM]  13.34 116.4 0 top
RH121  -  [R0402_0OHM]  9.79 108.27 0 top
RH122  -  [R0402_0OHM]  9.79 111.32 0 bottom
RH123  -  [R_0402]  21.69 132.62 270 top
RH124  -  [R_0402]  20.67 132.62 270 top
RH126  -  [R_0402]  23.72 131.67 90 bottom
RH127  -  [R_0402]  14.29 112.33 180 top
RH129  -  [R_0402]  13.34 111.32 0 top
RH131  -  [R_0402]  22.71 132.62 270 top
RH132  -  [R_0402]  23.72 132.62 270 top
RH133  -  [R_0402]  24.74 132.62 270 top
RH134  -  [R_0402]  21.69 132.62 270 bottom
RH137  -  [R_0402]  22.2 100.17 90 top
RH138  -  [R_0402]  18.13 96.04 270 top
RH139  -  [R_0402]  13.34 104.2 0 bottom
RH140  -  [R_0402]  13.34 105.22 0 top
RH141  -  [R_0402]  17.12 95.09 90 top
RH142  -  [R_0402]  13.34 106.24 0 bottom
RH144  -  [R_0402]  6.74 109.03 0 top
RH149  -  [R_0402]  39.22 101.12 270 top
RH150  -  [R0402_0OHM]  38.2 101.12 270 top
RH151  -  [R_0402]  14.35 119.55 180 top
RH152  -  [R_0402]  14.29 104.2 180 top
RH158  -  [R_0402]  22.2 101.12 270 bottom
RH160  -  [R_0402]  18.64 135.89 90 top
RH163  -  [R_0402]  13.34 122.57 0 bottom
RH164  -  [R_0402]  13.34 127.57 0 top
RH170  -  [R_0402]  14.29 103.19 180 bottom
RH171  -  [R_0402]  26.26 101.12 270 bottom
RH172  -  [R_0402]  19.15 101.12 270 bottom
RH173  -  [R_0402]  18.13 101.12 270 bottom
RH174  -  [R_0402]  25.25 101.12 270 bottom
RH175  -  [R_0402]  10.74 110.3 180 bottom
RH177  -  [R_0402]  14.29 106.24 180 top
RH178  -  [R_0402]  14.29 123.58 180 bottom
RH179  -  [R_0402]  14.29 125.54 180 top
RH181  -  [R_0402]  25.67 96.79 270 bottom
RH183  -  [R_0402]  22.71 135.89 90 top
RH195  -  [R_0805]  42.31 100.65 180 top
RH200  -  [R_0805]  32.36 133.62 270 top
RH201  -  [R0402_0OHM]  29.82 95.86 90 top
RH202  -  [R0603_0OHM]  30.08 99.68 90 top
RH203  -  [R_0402]  22.8 104.84 180 bottom
RH204  -  [R_0603]  28.55 99.68 90 top
RH205  -  [R0603_0OHM]  35.22 133.63 270 bottom
RH208  -  [R_0402]  10.29 119.95 0 bottom
RH211  -  [R_0603]  29.36 105.17 180 bottom
RH213  -  [R_0402]  10.29 120.97 0 bottom
RH215  -  [R_0805]  35.23 128.08 180 bottom
RH247  -  [TAIYO_LB2012T1R0M_2P]  49.39 115.13 180 top
RH248  -  [R_0805]  6.25 119.19 0 bottom
RH253  -  [R_0402]  30.83 95.86 90 top
RH256  -  [R_0402]  14.29 124.52 180 top
RH259  -  [R0402_0OHM]  23.21 100.17 90 bottom
RH262  -  [R_0402]  41.76 103.58 180 bottom
RH263  -  [R_0402]  24.65 95.84 90 bottom
RH266  -  [R_0402]  26.26 101.12 270 top
RH267  -  [R_0402]  21.18 101.12 270 top
RH268  -  [R_0402]  22.71 95.86 90 top
RH269  -  [R_0402]  13.34 126.56 0 bottom
RH270  -  [R_0402]  20.17 100.17 90 bottom
RH271  -  [R_0402]  21.69 96.8 270 top
RH272  -  [R_0402]  25.25 100.17 90 top
RH273  -  [R_0402]  14.29 127.57 180 bottom
RH274  -  [R_0402]  24.23 101.12 270 top
RH275  -  [R_0402]  20.55 102.97 90 bottom
RH276  -  [R_0805]  30.58 94.6 90 bottom
RH278  -  [R_0402]  7.94 121.73 180 bottom
RH280  -  [R0402_0OHM]  40.93 97.08 0 bottom
RH281  -  [R0402_0OHM]  40.95 98.1 0 bottom
RH282  -  [R_0402]  10.74 128.08 180 top
RH283  -  [R_0402]  66.52 112.55 270 top
RH284  -  [R_0402]  63.47 112.55 270 top
RH285  -  [R_0402]  62.46 112.55 270 top
RH286  -  [R0402_0OHM]  12.33 113.35 0 top
RH287  -  [R_0402]  13.34 122.55 0 top
RH288  -  [R_0603]  10.59 96.83 270 bottom
RH290  -  [R0402_0OHM]  28.29 101.12 270 bottom
RH298  -  [R_0402]  13.19 112.31 0 bottom
RH299  -  [R_0402]  13.19 113.32 0 bottom
RH300  -  [R_0402]  14.29 109.28 180 top
RH301  -  [R_0402]  10.74 109.28 180 top
RH302  -  [R_0402]  9.79 107.25 0 top
RH303  -  [R_0402]  9.79 106.11 0 top
RH304  -  [R_0402]  14.29 107.25 180 bottom
RH305  -  [R_0402]  14.29 103.19 180 top
RH306  -  [R_0402]  14.29 105.22 180 bottom
RH307  -  [R0402_0OHM]  30.83 131.67 90 bottom
RH308  -  [R0402_0OHM]  31.85 131.67 90 bottom
RH309  -  [R0402_0OHM]  25.79 132.65 0 top
RH310  -  [R0402_0OHM]  25.75 131.67 90 bottom
RH311  -  [R_0402]  21.69 136.84 270 top
RH312  -  [R0402_0OHM]  24.74 131.67 90 bottom
RH313  -  [R_0402]  18.64 132.62 270 top
RH314  -  [R_0402]  19.66 132.62 270 top
RH315  -  [R_0402]  20.67 136.84 270 top
RH316  -  [R_0402]  20.67 131.67 90 bottom
RH317  -  [R_0402]  22.71 132.62 270 bottom
RH318  -  [R_0402]  14.07 100.17 90 bottom
RH319  -  [R_0402]  13.34 111.32 0 bottom
RH320  -  [R0402_0OHM]  13.34 110.3 0 top
RH321  -  [R_0402]  10.77 112.33 180 bottom
RH323  -  [R0402_0OHM]  13.34 108.27 0 top
RH324  -  [R_0402]  13.34 128.59 0 bottom
RH325  -  [R_0402]  13.34 125.6 0 bottom
RH326  -  [R_0402]  13.34 124.6 0 bottom
RH327  -  [R_0402]  17.75 132.62 270 bottom
RH328  -  [R_0402]  10.29 126.05 0 bottom
RH329  -  [R_0402]  10.29 125.03 0 bottom
RH330  -  [R_0402]  19.66 132.62 270 bottom
RH331  -  [R_0402]  13.34 126.56 0 top
RH332  -  [R_0402]  15.72 132.62 270 bottom
RH333  -  [R_0402]  18.64 131.67 90 bottom
RH334  -  [R0402_0OHM]  17.12 128.55 270 bottom
RH335  -  [R0402_0OHM]  9.79 101.16 0 top
RH336  -  [R0402_0OHM]  9.79 103.19 0 top
RH337  -  [R_0402]  12.38 101.25 90 top
RH338  -  [R0402_0OHM]  9.79 102.17 0 top
RH339  -  [R0402_0OHM]  13.4 118.53 0 top
RH340  -  [R_0402]  16.74 132.62 270 bottom
RH341  -  [R0402_0OHM]  13.4 117.51 0 top
RH342  -  [R_0402]  17.63 131.67 90 top
RH343  -  [R0402_0OHM]  14.29 102.17 180 top
RH344  -  [R_0402]  32.25 122.35 180 bottom
RH345  -  [R_0402]  51.62 104.29 180 bottom
RH346  -  [R_0402]  51.62 105.31 180 bottom
RH347  -  [R_0402]  51.62 106.32 180 bottom
RH348  -  [R_0402]  50.67 107.34 0 bottom
RH349  -  [R_0402]  51.63 108.78 180 bottom
RH350  -  [R_0402]  50.68 109.92 0 bottom
RH353  -  [R_0402]  16.1 96.8 270 bottom
RH354  -  [R_0402]  16.1 100.17 90 top
RH355  -  [R_0402]  14.35 120.56 180 top
RH356  -  [R0402_0OHM]  10.74 112.33 180 top
RH357  -  [R_0402]  7.21 121.7 270 top
RH358  -  [R_0402]  37.18 100.17 90 top
RH359  -  [R0402_0OHM]  20.17 100.17 90 top
RPH1  -  [RP_1206_8P4R]  10.7 118.75 90 top
RPH2  -  [RP_1206_8P4R]  5.11 110.37 90 top
T1  -  [TPC12]  74.78 68.39 180 bottom
T2  -  [TPC12]  94.84 51.37 180 bottom
T3  -  [TPC12]  92.94 67.37 180 bottom
T4  -  [TPC12]  94.22 64.16 180 bottom
T5  -  [TPC12]  99.92 70.42 180 bottom
T6  -  [TPC12]  91.92 59.37 180 bottom
T7  -  [TPC12]  72.62 74.87 180 bottom
T8  -  [TPC12]  74.42 76.44 180 bottom
T9  -  [TPC12]  69.71 74.47 180 bottom
T10  -  [TPC12]  67 72.42 180 bottom
T11  -  [TPC12]  74.9 74.74 180 bottom
T12  -  [TPC12]  73 69.41 180 bottom
T13  -  [TPC12]  73.76 72.45 180 bottom
T14  -  [TPC12]  92.05 56.58 180 bottom
T15  -  [TPC12]  85.89 49.7 180 bottom
T16  -  [TPC12]  84.82 48.5 180 bottom
T17  -  [TPC12]  83.92 47.44 180 bottom
T18  -  [TPC12]  74.9 70.3 180 bottom
T19  -  [TPC12]  62.91 80.7 0 top
T20  -  [TPC12]  65.45 81.59 0 top
T21  -  [TPC12]  66.48 84.14 0 top
T22  -  [TPC12]  60.36 81.22 0 top
T23  -  [TPC12]  64.15 81.52 0 top
T24  -  [TPC12]  75.54 47.18 180 bottom
T25  -  [TPC12]  76.81 47.44 180 bottom
T26  -  [TPC12]  77.84 46.6 180 bottom
T27  -  [TPC12]  74.95 43.68 180 bottom
T28  -  [TPC12]  67.45 34.86 0 top
T29  -  [TPC12]  75.92 48.45 180 bottom
T30  -  [TPC12]  68.05 35.99 0 top
T31  -  [TPC12]  77.82 48.32 180 bottom
T32  -  [TPC12]  67.19 37.25 0 top
T33  -  [TPC12]  76.81 45.66 180 bottom
T34  -  [TPC12]  58.65 43.26 0 top
T35  -  [TPC12]  77.86 41.53 180 bottom
T36  -  [TPC12]  60.3 43.24 0 top
T37  -  [TPC12]  71.22 35.52 0 top
T38  -  [TPC12]  70 37.39 0 top
T39  -  [TPC12]  71.4 36.88 0 top
T40  -  [TPC12]  73.14 37.14 0 top
T41  -  [TPC12]  70.97 44.51 180 bottom
T42  -  [TPC12]  68.86 69.81 180 bottom
T43  -  [TPC12]  68.6 37.22 0 top
T44  -  [TPC12]  67.83 71.13 180 bottom
T45  -  [TPC12]  72.43 34.75 0 top
T46  -  [TPC12]  72.48 36.03 0 top
T47  -  [TPC12]  80.3 49.7 180 bottom
T48  -  [TPC12]  82.9 42.48 180 bottom
T49  -  [TPC12]  86.19 48.43 180 bottom
T50  -  [TPC12]  99.16 81.6 0 top
T51  -  [TPC12]  100.81 81.85 0 top
T52  -  [TPC12]  102.46 81.85 0 top
T53  -  [TPC12]  99.92 42.48 180 bottom
T55  -  [TPC12]  73.89 71.18 180 bottom
T56  -  [TPC12]  13.05 101.16 270 bottom
T57  -  [TPC12]  22.07 110.87 270 bottom
T58  -  [TPC12]  19 109.97 270 bottom
T59  -  [TPC12]  20.2 105.49 270 bottom
T60  -  [TPC12]  71.98 70.42 180 bottom
T61  -  [TPC12]  54.71 170.16 180 bottom
T62  -  [TPC12]  20.09 111.87 270 bottom
T63  -  [TPC12]  34.07 111.37 270 bottom
T64  -  [TPC12]  68.68 73.47 180 bottom
T68  -  [TPC12]  70.97 73.47 180 bottom
T69  -  [TPC12]  72.74 73.47 180 bottom
T70  -  [TPC12]  74.78 73.47 180 bottom
T71  -  [TPC12]  69.9 71.12 180 bottom
T72  -  [TPC12]  71.22 74.74 180 bottom
T73  -  [TPC12]  74.01 81.6 0 top
T74  -  [TPC12]  71.35 82.61 0 top
T75  -  [TPC12]  68.55 83 0 top
T76  -  [TPC12]  70.46 81.6 0 top
T77  -  [TPC12]  68.43 75.76 180 bottom
T78  -  [TPC12]  69.82 76.39 180 bottom
T79  -  [TPC12]  68.81 81.6 0 top
T80  -  [TPC12]  67.41 82.23 0 top
T104  -  [TPC12]  21.23 107.61 270 bottom
T106  -  [TPC12]  24.18 110.22 180 bottom
T107  -  [TPC12]  19.33 106.97 180 bottom
T108  -  [TPC12]  24.64 121.11 180 bottom
T109  -  [TPC12]  15.72 123.89 180 bottom
T117  -  [TPC12]  230.12 68.68 180 bottom
T142  -  [TPC12]  128.42 161.35 0 top
T143  -  [TPC12]  128.43 162.65 0 top
T156  -  [TAIMA_IH-115-F_24P]  94.21 147.53 180 bottom
U2  -  [SLGC55584AVTR_TDFN8_2X2]  275.32 80.86 0 bottom
U3  -  [TC7SH125FU_SSOP5]  79.71 132.26 0 top
U4  -  [RT9818A-44GU3_SC70-3]  179.78 142.13 90 bottom
U7  -  [TC7SH08FU_SSOP5]  182.36 146.94 180 bottom
U8  -  [SN74AHC1G08DCKR_SC70-5]  212.33 159.41 180 top
U9  -  [PS8336BQFN56GTR-A0_QFN56_7X7]  46.25 143.51 90 top
U10  -  [TC7SH08FU_SSOP5]  144.01 169.92 180 top
U11  -  [TS3DV20812RHHR_VQFN36_6X6]  73.22 136.82 180 top
U12  -  [PI2DBS212ZHEX_TQFN28_5P5X3P5]  32.32 149.62 180 top
U13  -  [TS3DV20812RHHR_VQFN36_6X6]  60.77 138.09 180 top
U14  -  [SN74AHC1G08DCKR_SC70-5]  210.92 105.08 90 bottom
U15  -  [TC7SH08FU_SSOP5]  129.45 156.16 270 top
U16  -  [74AHC1G09GW_TSSOP5]  210.68 134.69 180 top
U17  -  [74AHC1G09GW_TSSOP5]  204.83 153.75 270 bottom
U18  -  [EMC4002-HZH-C_QFN48_7X7]  138.57 156.36 0 top
U19  -  [MAX14885EETLLFT_TQFN40_5X5]  64.04 155.79 270 bottom
U20  -  [PI3C3125LEX_TSSOP14]  112.96 145.75 0 top
U21  -  [TC7SET04FU_SSOP5]  106.85 149.81 270 top
U22  -  [PS8330BQFN48GTR-A0_QFN48_7X7]  280.3 71.54 90 bottom
U25  -  [SN74AHC1G08DCKR_SC70-5]  211.42 109.38 270 bottom
U26  -  [PS8520BTQFN20GTR2_TQFN20_4X4]  210.68 86.8 0 bottom
U27  -  [SN74AHC1G08DCKR_SC70-5]  193.9 87.35 270 top
U31  -  [82579_QFN48_6X6]  121.08 163.05 270 top
U32  -  [PI3L720ZHEX_TQFN42_9X3P5]  127.8 145.04 180 top
U37  -  [SSX44-B-D-T1_TSSOP28]  166.31 97.91 0 top
U39  -  [AT97SC3204-X2A14-AB_TSSOP28]  166.31 98.76 0 top
U40  -  [SRV05-4PTCT_SOT23-6]  265.45 33.07 90 bottom
U45  -  [TPS2560DRCR-PG1P1_SON10_3X3]  291.28 57.89 90 bottom
U46  -  [ECE5048-LZY_DQFN132_11X11]  240.58 66.75 180 bottom
U47  -  [TC7SH08FU_SSOP5]  244.77 67.99 90 bottom
U48  -  [TPS2560DRCR-PG1P1_SON10_3X3]  16.41 161.08 270 top
U50  -  [TC7SH08FU_SSOP5]  27.67 13.97 180 top
U52  -  [W25Q64CVSSIG_SO8]  56.05 105.86 90 top
U53  -  [W25Q32BVSSIG_SO8]  56.05 99.51 90 top
U54  -  [MEC5055-LZY_DQFN132_11X11]  161.27 150.88 270 top
U58  -  [TC7SH08FU_SSOP5]  247.38 61.85 180 bottom
U59  -  [INA211AIDCKRG4_SC70-6]  167.11 175.2 270 top
U60  -  [INA219AIDCNRG4_SOT23-8]  158.09 173.52 90 top
U88  -  [LNG3DMTR_LGA16_3X3]  124.83 101.07 0 top
U625  -  [PS8710BTQFN24GTR-A1_TQFN24_4X4]  267.58 76.46 0 bottom
U626  -  [PS8710BTQFN24GTR-A1_TQFN24_4X4]  255.14 76.46 0 bottom
U627  -  [SN74AHC1G02DCKR_SC70-5]  44.01 167.71 90 top
UC1  -  [74AHC1G09GW_TSSOP5]  95.24 86.56 180 top
UC2  -  [SN74LVC1G07DCKR_SC70-5]  67.3 87.04 180 top
UC3  -  [74AHC1G09GW_TSSOP5]  19.26 95.56 0 top
UC4  -  [TC7SH08FU_SSOP5]  39.86 96.73 270 bottom
UH3  -  [TC7SH08FU_SSOP5]  8.29 103.3 90 top
UH4  -  [BD82PPSM-QNHN-A0_BGA_989P]  17.86 104.54 270 top
Y3  -  [Y_X3G025000DI1H-H_4P]  113.3 156.44 0 top
Y6  -  [Y_Q13FC1350000_2P]  165.18 158.05 180 top
YH1  -  [Y_Q13FC1350000_2P]  11 115.13 180 top
YH2  -  [Y_Q22FA2380049900_4P]  26.35 136.75 180 top

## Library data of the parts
C1 C3 C328 C332 = C_0603: room: MXM
C2 = C_1206: room: MXM
C4 C7 C8 C90 C91 = C_0402: room: MXM
C12-C15 C18-C23 C1181 = C_0402: room: CRT
C24 C86-C88 C92-C96 C257-C259 C295 C302-C304 C306-C311 C365 C424-C427 C431 C438-C444 C496 C497 C500-C503 C749 C750 C769 C777 C1174 C1183-C1186 C1188 C1332-C1341 CC92 CH8 CH20-CH23 CH100 PC6 PC17-PC21 PC120 PC121 PC198 PC199 PC218 PC299 PC499 PC511 PC599 PC743 PC749 PC753 PC791-PC798 PC918 PC923 PC926 PC942 PC999 = C_0402
C45 C48 C550-C554 CE3 CE4 = C_0402: room: TPM
C52 C53 C56 = C_0402: room: USH
C242 C245-C247 C251-C254 C389 C390 C402 C405 C410 C437 = C_0402: room: DP/HDMI MUX
C243 C248 C292 C293 C297 C298 = C_0402: room: LVDS
C244 C255 C256 C305 C371-C380 = C_0402: room: EDP
C249 C296 = C_0603: room: LVDS
C250 = C_0603: room: EDP
C260 C766 CH37 PC31 PC929 = C_0603
C272 C287 C288 C294 C327 C333-C336 C339-C341 C343 C344 C346-C350 C364 C370 = C_0402: room: THERMAL
C279-C286 C313 C397 C398 = C_0402: room: DP
C289 C290 C720 C726-C729 C731-C739 C741-C747 C757 = C_0402: room: KBC
C299 C301 = C_0402: room: CAM
C300 = C_0805: room: CAM
C323 C324 = C_D2: room: USB3.0
C329 C330 = C_0805: room: THERMAL
C337 = C_0402: room: HDMI
C338 = C_0805: room: HDMI
C351 = C_0402: room: +5V_MXM SOURCE
C352 C362 = C_0603: room: +3V_MXM SOURCE
C353 C356 = C_0805: room: +5V_MXM SOURCE
C354 = C_0402: room: +3V_MXM SOURCE
C355 = C_0603: room: +5V_MXM SOURCE
C357 C449 = C_0805: room: +3V_MXM SOURCE
C359 C366-C369 = C_0402: room: DP_SW
C383-C386 C395 C403 C404 C406-C409 C411-C415 C418-C423 = C_0402: room: HDD
C387 C388 CH2-CH5 CH18 CH19 CH31-CH35 CH43 CH45-CH52 CH54-CH57 CH59-CH63 CH66-CH69 CH72 CH74-CH79 CH81-CH84 CH86-CH93 CH96-CH99 CH101-CH104 = C_0402: room: PCH
C391 = C_0402: room: FFS
C392 = C_0603: room: FFS
C393 = C_0603: room: +5V_HDD SOURCE
C394 = C_0805: room: +5V_HDD SOURCE
C416 = C_0603: room: +5VMOD SOURCE
C417 = C_0805: room: +5VMOD SOURCE
C428-C430 C432-C434 = C_0402: room: ODD
C435 C436 C445-C448 C640 C641 = C_0402: room: FLASH SW
C450-C457 C465 C487-C493 C670 C715 = C_0402: room: USB3.0
C458-C461 C463 C466-C474 C478 = C_0402: room: LAN
C462 C464 = C_0603: room: LAN
C475 = C_0603: room: +3.3V_LAN SOURCE
